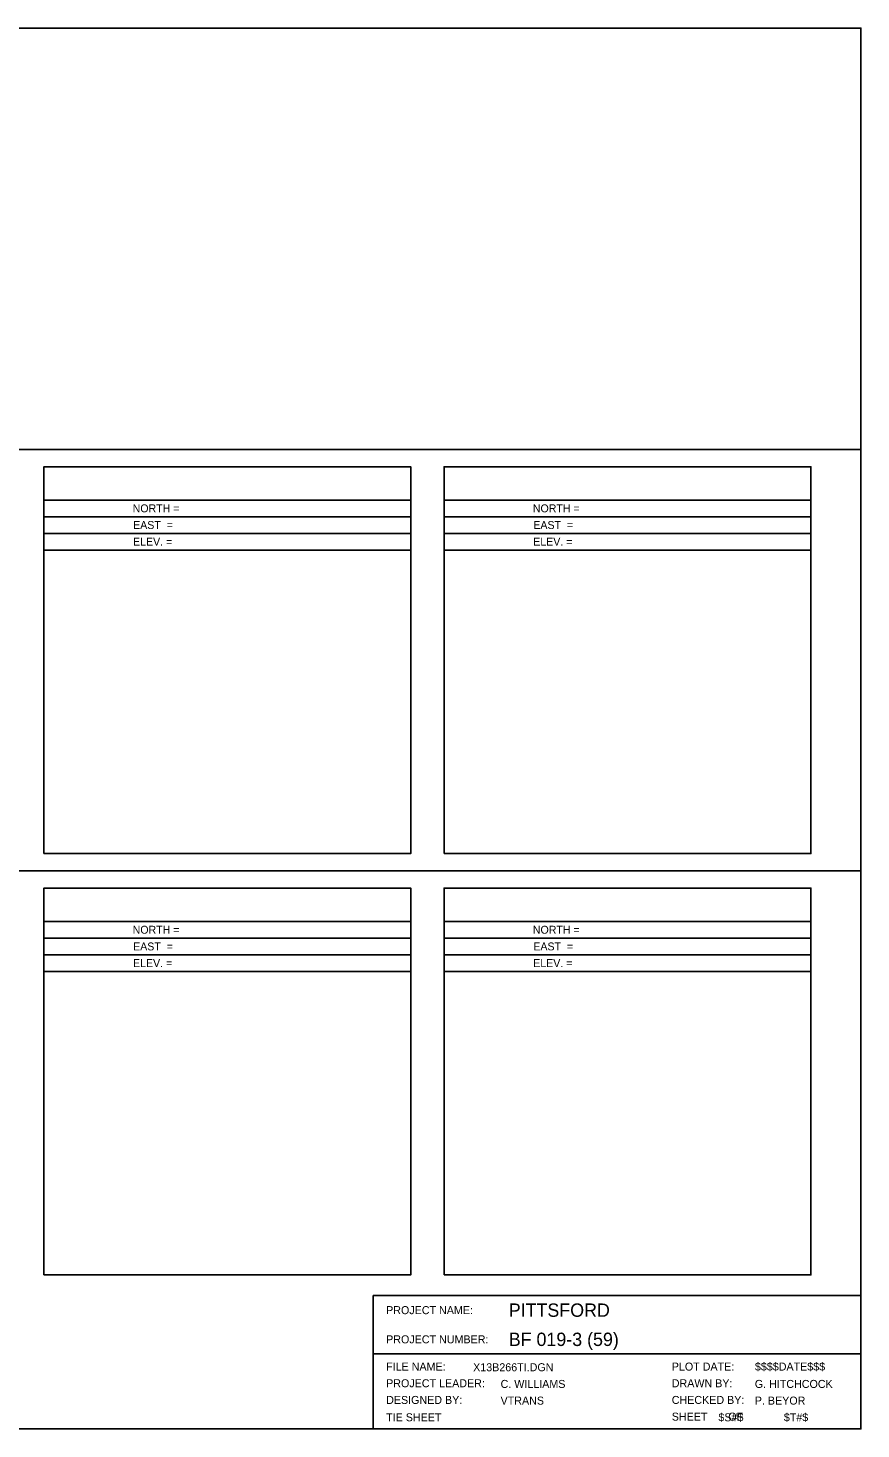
# Model space of a CAD drawing. Extents: x 1504239 to 1504879, y 438007 to 438427.
# Drawn here: x 1504629.5 to 1504879.3, y 438006.7 to 438426.7 of the extents above; entities that cross this region are included whole.
import ezdxf

# ---------------------------------------------------------------- set-up
doc = ezdxf.new("R2010")
doc.units = 0
doc.layers.add('NBL1', color=7, linetype='Continuous')
doc.layers.add('NBL2', color=7, linetype='Continuous')

msp = doc.modelspace()

# ---------------------------------------------------------------- linework, layer by layer
at = {"layer": 'NBL1'}
msp.add_line((1504733.02, 438029.19), (1504879.27, 438029.19), dxfattribs=at)
msp.add_lwpolyline([(1504239.27, 438006.69), (1504879.27, 438006.69), (1504879.27, 438426.69), (1504239.27, 438426.69)], close=True, dxfattribs=at)
msp.add_lwpolyline([(1504879.27, 438046.69), (1504733.02, 438046.69), (1504733.02, 438006.69)], dxfattribs=at)
at = {"layer": 'NBL2'}
for p, q in [((1504239.27, 438300.36), (1504879.27, 438300.36)), ((1504744.27, 438285.19), (1504634.27, 438285.19)), ((1504864.27, 438285.19), (1504754.27, 438285.19)), ((1504744.27, 438280.19), (1504634.27, 438280.19)), ((1504864.27, 438280.19), (1504754.27, 438280.19)), ((1504744.27, 438275.19), (1504634.27, 438275.19)), ((1504864.27, 438275.19), (1504754.27, 438275.19)), ((1504744.27, 438270.19), (1504634.27, 438270.19)), ((1504864.27, 438270.19), (1504754.27, 438270.19)), ((1504239.27, 438174.03), (1504879.27, 438174.03)), ((1504744.27, 438158.86), (1504634.27, 438158.86)), ((1504864.27, 438158.86), (1504754.27, 438158.86)), ((1504744.27, 438153.86), (1504634.27, 438153.86)), ((1504864.27, 438153.86), (1504754.27, 438153.86)), ((1504744.27, 438148.86), (1504634.27, 438148.86)), ((1504864.27, 438148.86), (1504754.27, 438148.86)), ((1504744.27, 438143.86), (1504634.27, 438143.86)), ((1504864.27, 438143.86), (1504754.27, 438143.86))]:
    msp.add_line(p, q, dxfattribs=at)
for points in [[(1504634.27, 438179.19), (1504744.27, 438179.19), (1504744.27, 438295.19), (1504634.27, 438295.19)], [(1504754.27, 438179.19), (1504864.27, 438179.19), (1504864.27, 438295.19), (1504754.27, 438295.19)], [(1504634.27, 438052.86), (1504744.27, 438052.86), (1504744.27, 438168.86), (1504634.27, 438168.86)], [(1504754.27, 438052.86), (1504864.27, 438052.86), (1504864.27, 438168.86), (1504754.27, 438168.86)]]:
    msp.add_lwpolyline(points, close=True, dxfattribs=at)

# ---------------------------------------------------------------- texts
at = {"layer": 'NBL1'}
for s, height, p in [('PROJECT NAME:', 2.4, (1504736.89, 438041.12)), ('PITTSFORD                 ', 4, (1504773.66, 438040.32)), ('PROJECT NUMBER:', 2.4, (1504736.89, 438032.37)), ('BF 019-3 (59)             ', 4, (1504773.66, 438031.57)), ('FILE NAME:', 2.4, (1504736.89, 438024.2)), ('     X13B266TI.DGN        ', 2.4, (1504758.52, 438024)), ('PLOT DATE:', 2.4, (1504822.54, 438024.2)), ('$$$$DATE$$$', 2.4, (1504847.47, 438024.2)), ('PROJECT LEADER:', 2.4, (1504736.89, 438019.2)), ('C. WILLIAMS         ', 2.4, (1504771.21, 438019)), ('DRAWN BY:', 2.4, (1504822.54, 438019.2)), ('G. HITCHCOCK ', 2.4, (1504847.44, 438019)), ('DESIGNED BY:', 2.4, (1504736.89, 438014.2)), ('VTRANS              ', 2.4, (1504771.21, 438014)), ('CHECKED BY:', 2.4, (1504822.54, 438014.2)), ('P. BEYOR     ', 2.4, (1504847.44, 438014)), ('TIE SHEET                         ', 2.4, (1504736.89, 438009)), ('SHEET       OF', 2.4, (1504822.54, 438009.2)), ('$S#$ ', 2.4, (1504836.52, 438009)), ('$T#$   ', 2.4, (1504856.14, 438009))]:
    msp.add_text(s, height=height, dxfattribs=at).set_placement(p)
at = {"layer": 'NBL2'}
for s, p in [('NORTH =             ', (1504660.89, 438281.51)), ('NORTH =             ', (1504780.89, 438281.51)), ('EAST  =             ', (1504661.03, 438276.51)), ('EAST  =             ', (1504781.03, 438276.51)), ('ELEV. =             ', (1504661, 438271.51)), ('ELEV. =             ', (1504781, 438271.51)), ('NORTH =             ', (1504660.89, 438155.17)), ('NORTH =             ', (1504780.89, 438155.17)), ('EAST  =             ', (1504661.03, 438150.17)), ('EAST  =             ', (1504781.03, 438150.17)), ('ELEV. =             ', (1504661, 438145.17)), ('ELEV. =             ', (1504781, 438145.17))]:
    msp.add_text(s, height=2.375, dxfattribs=at).set_placement(p)

doc.saveas('drawing.dxf')
